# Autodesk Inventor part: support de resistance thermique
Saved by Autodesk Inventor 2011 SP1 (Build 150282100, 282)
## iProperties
Created: 2010-12
Part Number: support de resistance thermique
Document SubType Name: Modeling
Designer: eric
Density: 1 g/cm^3
Author: eric
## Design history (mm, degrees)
feature "Base1"
node "Solide1"
node "Corps solides"
node "Corps surfaciques"
